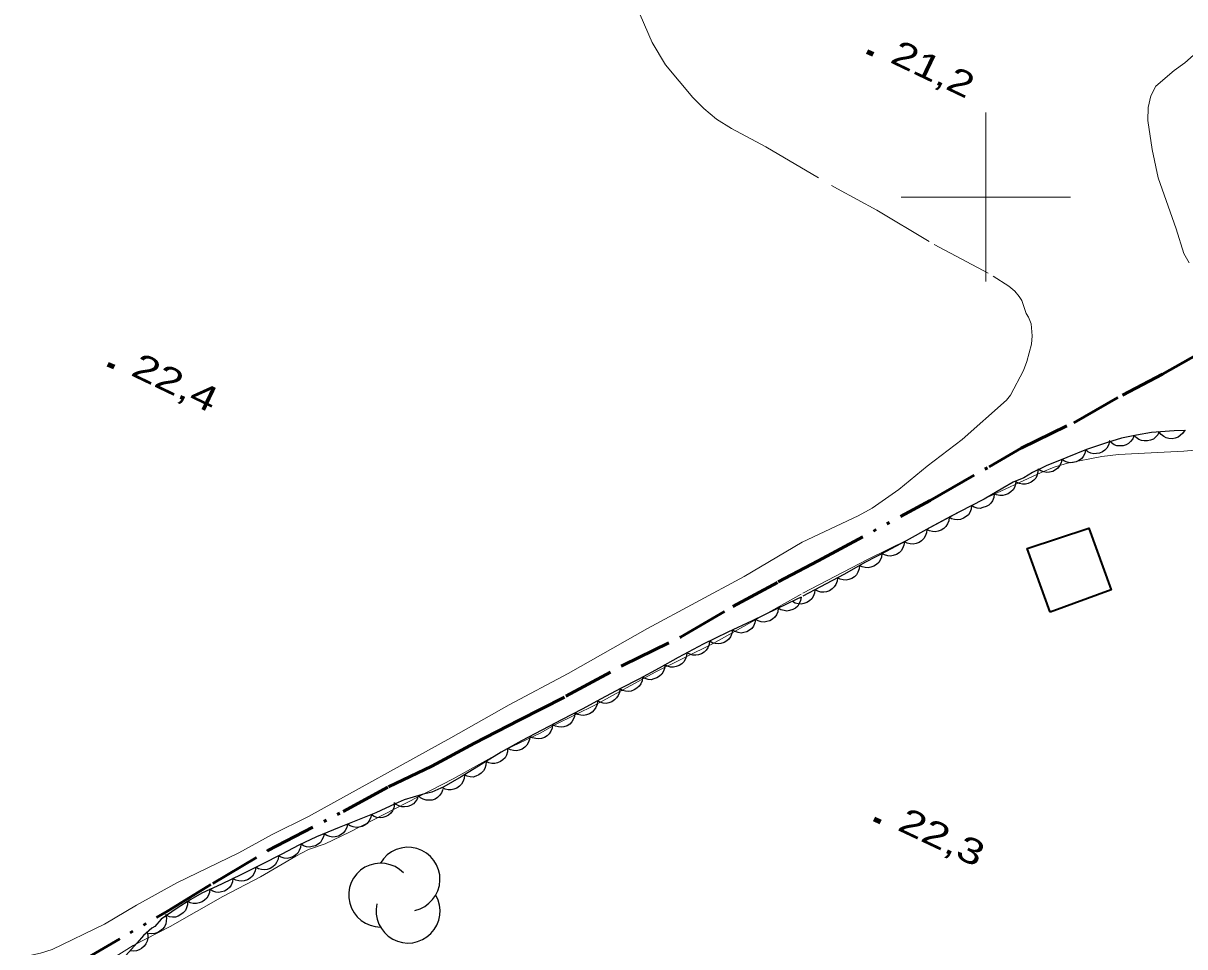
# Model space of a CAD drawing. Extents: x 356765 to 358572, y 5103174 to 5104650.
# Drawn here: x 357043.2 to 357111.7, y 5104255.7 to 5104310.3 of the extents above; entities that cross this region are included whole.
import ezdxf

# ---------------------------------------------------------------- set-up
doc = ezdxf.new("R2010")
doc.units = 0
doc.header["$LTSCALE"] = 0.6
for name, pattern in [('DASH_DOUBLE_DOT', [9.2, 5, -1.2, 0.3, -1.2, 0.3, -1.2]), ('DOT_DASHED', [7.7, 5, -1.2, 0.3, -1.2]), ('LONG_DASHED', [7.5, 6, -1.5])]:
    doc.linetypes.add(name, pattern=pattern)
for name, color, linetype, lineweight in [('2', 7, 'Continuous', 13), ('3', 7, 'Continuous', 140), ('31', 7, 'Continuous', 70), ('4', 7, 'Continuous', 90), ('44', 7, 'Continuous', 25), ('61', 7, 'Continuous', 13)]:
    doc.layers.add(name, color=color, linetype=linetype, lineweight=lineweight)

msp = doc.modelspace()

# ---------------------------------------------------------------- linework, layer by layer
at = {"layer": '2', "linetype": 'LONG_DASHED'}
for points in [[(357079.59, 5104310.76), (357080.31, 5104309.13), (357081.09, 5104307.8), (357082.7, 5104305.87), (357083.36, 5104305.22), (357084.11, 5104304.59), (357084.98, 5104304.05), (357087.02, 5104302.96), (357091.24, 5104300.48), (357093.57, 5104299.23), (357096.96, 5104297.2), (357100.44, 5104295.33), (357101.35, 5104294.74), (357101.71, 5104294.43), (357101.96, 5104294.13), (357102.12, 5104293.88), (357102.38, 5104293.12), (357102.53, 5104292.9), (357102.67, 5104292.51), (357102.73, 5104291.79), (357102.69, 5104291.3), (357102.43, 5104290.28), (357102.23, 5104289.76), (357101.45, 5104288.3), (357101.23, 5104287.99)], [(357112.01, 5104296.12), (357111.69, 5104296.67), (357111.24, 5104298.11), (357110.18, 5104301.13), (357109.82, 5104302.8), (357109.57, 5104304.51), (357109.59, 5104305.28), (357109.74, 5104305.97), (357110.04, 5104306.54), (357111.11, 5104307.48), (357111.74, 5104307.92), (357112.27, 5104308.38)]]:
    msp.add_lwpolyline(points, dxfattribs=at)
at = {"layer": '2'}
for points in [[(357126.22, 5104296.62), (357124.12, 5104295), (357123.48, 5104294.44), (357122.62, 5104293.59), (357121.99, 5104292.88), (357121.01, 5104291.3), (357120.74, 5104290.63), (357120.54, 5104289.91), (357120.33, 5104289.5), (357118.51, 5104286.99), (357118.07, 5104286.68), (357116.81, 5104286.18), (357113.43, 5104285.23), (357112.56, 5104285.07), (357111.68, 5104284.98), (357107.84, 5104284.79), (357106.84, 5104284.68), (357104.83, 5104284.28), (357104.04, 5104284.04), (357103.26, 5104283.73), (357099.86, 5104282.15), (357095.38, 5104279.75), (357093.01, 5104278.59), (357089.2, 5104276.59)], [(357043.18, 5104255.03), (357043.56, 5104255.2), (357044.2, 5104255.33), (357044.89, 5104255.55), (357047.98, 5104257.05), (357049.87, 5104258.18), (357052.24, 5104259.48), (357055.91, 5104261.26), (357057.87, 5104262.34), (357060.02, 5104263.41), (357068.42, 5104268.05), (357071.86, 5104270.01), (357075.34, 5104271.86), (357080.04, 5104274.51), (357085.73, 5104277.58), (357089.17, 5104279.61), (357092.47, 5104281.17), (357093.29, 5104281.63), (357094.86, 5104282.73), (357096.54, 5104284.11), (357098.6, 5104285.67), (357101.23, 5104287.99)], [(357089.1, 5104276.54), (357083.9, 5104273.62), (357080.48, 5104271.93), (357076.96, 5104270.01), (357074.56, 5104268.82), (357073.69, 5104268.33), (357071.67, 5104267.36), (357068.56, 5104265.63), (357062.43, 5104262.49), (357061, 5104261.8), (357060.02, 5104261.46), (357059.28, 5104261.07), (357057.18, 5104259.84), (357054.96, 5104258.69), (357051.86, 5104256.92), (357049.67, 5104255.79), (357047.76, 5104254.59), (357046.74, 5104254.01), (357044.55, 5104252.92)]]:
    msp.add_lwpolyline(points, dxfattribs=at)
at = {"layer": '3'}
for p, q in [((357092.99, 5104308.6), (357093.35, 5104308.43)), ((357048.18, 5104290.13), (357048.54, 5104289.96)), ((357093.41, 5104263.27), (357093.78, 5104263.1))]:
    msp.add_line(p, q, dxfattribs=at)
at = {"layer": '31', "lineweight": 35}
msp.add_lwpolyline([(357103.79, 5104275.48), (357102.45, 5104279.24), (357106.08, 5104280.43), (357107.41, 5104276.8), (357103.79, 5104275.48)], close=True, dxfattribs=at)
at = {"layer": '4', "linetype": 'DASH_DOUBLE_DOT', "lineweight": 53}
msp.add_lwpolyline([(357046.29, 5104254.66), (357051.69, 5104257.82), (357054.38, 5104259.46), (357057.62, 5104261.39), (357062.07, 5104263.71), (357064.74, 5104265.16), (357067.3, 5104266.39), (357069.82, 5104267.73), (357072.45, 5104269.1), (357075.21, 5104270.51), (357078.6, 5104272.35), (357081.98, 5104274), (357085.06, 5104275.81), (357087.74, 5104277.26), (357090.1, 5104278.5), (357096.72, 5104282.07), (357100.19, 5104284.06), (357102.09, 5104285.16), (357105.19, 5104286.67), (357108.07, 5104288.3), (357110.43, 5104289.54), (357112.88, 5104290.92)], dxfattribs=at)
at = {"layer": '44', "linetype": 'DOT_DASHED'}
for points in [[(357111.79, 5104286.21), (357111.11, 5104286.18), (357109.78, 5104286.08), (357108.89, 5104285.94), (357108.02, 5104285.75), (357107.18, 5104285.5), (357105.95, 5104285.08), (357104.79, 5104284.62), (357103.56, 5104284.12), (357102.75, 5104283.73), (357102.24, 5104283.41), (357101.61, 5104283.15), (357101.01, 5104282.8), (357099.9, 5104282.15), (357099.09, 5104281.73), (357097.95, 5104281.15), (357096.68, 5104280.46), (357095.3, 5104279.69), (357094.11, 5104279.07), (357092.9, 5104278.43), (357091.61, 5104277.71), (357090.25, 5104276.97), (357089.2, 5104276.42)], [(357089.1, 5104276.37), (357088.8, 5104276.22), (357087.67, 5104275.67), (357086.21, 5104274.96), (357084.77, 5104274.29), (357083.32, 5104273.58), (357081.84, 5104272.8), (357080.71, 5104272.17), (357079.56, 5104271.54), (357078.43, 5104270.96), (357077.3, 5104270.36), (357076.17, 5104269.75), (357075, 5104269.13), (357073.8, 5104268.51), (357072.59, 5104267.88), (357071.4, 5104267.2), (357070.21, 5104266.47), (357069.04, 5104265.75), (357068, 5104265.16), (357067.29, 5104264.84), (357066.72, 5104264.7), (357065.67, 5104264.4), (357065.14, 5104264.15), (357064, 5104263.62), (357063.2, 5104263.3), (357061.82, 5104262.75), (357060.49, 5104262.2), (357059.44, 5104261.71), (357058.45, 5104261.19), (357057.25, 5104260.58), (357056.07, 5104259.99), (357054.88, 5104259.41), (357053.73, 5104258.87), (357053.07, 5104258.5), (357052.26, 5104257.99), (357051.32, 5104257.34), (357050.95, 5104256.92), (357050.78, 5104256.82), (357050.27, 5104256.38), (357049.9, 5104255.95), (357048.9, 5104254.83)]]:
    msp.add_lwpolyline(points, dxfattribs=at)
at = {"layer": '44'}
for points in [[(357108.76, 5104285.91), (357108.68, 5104285.72), (357108.55, 5104285.56), (357108.43, 5104285.44), (357108.28, 5104285.36), (357108.1, 5104285.31), (357107.91, 5104285.3), (357107.74, 5104285.31), (357107.58, 5104285.37), (357107.42, 5104285.47), (357107.29, 5104285.59)], [(357110.24, 5104286.15), (357110.15, 5104285.96), (357110.01, 5104285.81), (357109.89, 5104285.7), (357109.72, 5104285.63), (357109.54, 5104285.59), (357109.35, 5104285.59), (357109.19, 5104285.61), (357109.03, 5104285.68), (357108.88, 5104285.79), (357108.75, 5104285.92)], [(357111.74, 5104286.23), (357111.63, 5104286.05), (357111.48, 5104285.91), (357111.35, 5104285.81), (357111.18, 5104285.75), (357111, 5104285.72), (357110.81, 5104285.74), (357110.65, 5104285.77), (357110.5, 5104285.86), (357110.35, 5104285.97), (357110.24, 5104286.11)], [(357107.3, 5104285.54), (357107.25, 5104285.34), (357107.14, 5104285.17), (357107.03, 5104285.04), (357106.89, 5104284.94), (357106.72, 5104284.87), (357106.53, 5104284.84), (357106.37, 5104284.83), (357106.2, 5104284.87), (357106.03, 5104284.95), (357105.88, 5104285.06)], [(357104.49, 5104284.5), (357104.45, 5104284.29), (357104.35, 5104284.12), (357104.25, 5104283.98), (357104.11, 5104283.88), (357103.95, 5104283.79), (357103.76, 5104283.75), (357103.6, 5104283.73), (357103.42, 5104283.77), (357103.25, 5104283.83), (357103.1, 5104283.93)], [(357105.88, 5104285.05), (357105.84, 5104284.85), (357105.74, 5104284.67), (357105.64, 5104284.54), (357105.5, 5104284.44), (357105.33, 5104284.35), (357105.15, 5104284.31), (357104.98, 5104284.3), (357104.81, 5104284.33), (357104.64, 5104284.4), (357104.49, 5104284.5)], [(357103.09, 5104283.94), (357103.08, 5104283.74), (357103.02, 5104283.54), (357102.95, 5104283.4), (357102.83, 5104283.27), (357102.68, 5104283.16), (357102.5, 5104283.08), (357102.34, 5104283.04), (357102.17, 5104283.04), (357101.99, 5104283.07), (357101.82, 5104283.15)], [(357101.77, 5104283.24), (357101.76, 5104283.04), (357101.69, 5104282.85), (357101.61, 5104282.7), (357101.48, 5104282.58), (357101.33, 5104282.47), (357101.15, 5104282.4), (357101, 5104282.36), (357100.82, 5104282.37), (357100.64, 5104282.41), (357100.48, 5104282.49)], [(357100.49, 5104282.46), (357100.47, 5104282.25), (357100.39, 5104282.06), (357100.3, 5104281.92), (357100.17, 5104281.8), (357100.02, 5104281.71), (357099.83, 5104281.65), (357099.67, 5104281.61), (357099.5, 5104281.63), (357099.32, 5104281.68), (357099.16, 5104281.77)], [(357099.16, 5104281.77), (357099.14, 5104281.56), (357099.05, 5104281.37), (357098.97, 5104281.23), (357098.84, 5104281.12), (357098.68, 5104281.02), (357098.5, 5104280.96), (357098.34, 5104280.93), (357098.16, 5104280.95), (357097.98, 5104281), (357097.83, 5104281.09)], [(357097.83, 5104281.08), (357097.81, 5104280.88), (357097.73, 5104280.69), (357097.65, 5104280.54), (357097.52, 5104280.42), (357097.36, 5104280.32), (357097.18, 5104280.26), (357097.02, 5104280.22), (357096.85, 5104280.24), (357096.67, 5104280.28), (357096.51, 5104280.37)], [(357096.51, 5104280.37), (357096.49, 5104280.16), (357096.42, 5104279.97), (357096.34, 5104279.82), (357096.21, 5104279.7), (357096.06, 5104279.6), (357095.88, 5104279.53), (357095.72, 5104279.5), (357095.54, 5104279.51), (357095.36, 5104279.55), (357095.2, 5104279.63)], [(357095.2, 5104279.64), (357095.17, 5104279.43), (357095.09, 5104279.24), (357095.01, 5104279.1), (357094.88, 5104278.98), (357094.72, 5104278.88), (357094.54, 5104278.83), (357094.38, 5104278.79), (357094.21, 5104278.81), (357094.03, 5104278.86), (357093.87, 5104278.94)], [(357093.87, 5104278.94), (357093.85, 5104278.73), (357093.77, 5104278.55), (357093.68, 5104278.41), (357093.55, 5104278.29), (357093.4, 5104278.19), (357093.22, 5104278.13), (357093.06, 5104278.09), (357092.88, 5104278.11), (357092.7, 5104278.16), (357092.54, 5104278.24)], [(357092.55, 5104278.23), (357092.53, 5104278.03), (357092.45, 5104277.84), (357092.37, 5104277.69), (357092.25, 5104277.57), (357092.09, 5104277.47), (357091.91, 5104277.4), (357091.75, 5104277.36), (357091.58, 5104277.38), (357091.4, 5104277.42), (357091.24, 5104277.5)], [(357091.24, 5104277.51), (357091.22, 5104277.3), (357091.14, 5104277.11), (357091.05, 5104276.97), (357090.93, 5104276.85), (357090.77, 5104276.74), (357090.59, 5104276.68), (357090.43, 5104276.65), (357090.26, 5104276.66), (357090.08, 5104276.71), (357089.92, 5104276.79)], [(357089.1, 5104276.37), (357089.07, 5104276.16), (357088.99, 5104275.98), (357088.9, 5104275.84), (357088.76, 5104275.72), (357088.61, 5104275.63), (357088.42, 5104275.57), (357088.26, 5104275.54), (357088.09, 5104275.57), (357087.91, 5104275.62), (357087.75, 5104275.71)], [(357089.91, 5104276.79), (357089.89, 5104276.59), (357089.81, 5104276.4), (357089.73, 5104276.26), (357089.6, 5104276.14), (357089.44, 5104276.04), (357089.26, 5104275.98), (357089.1, 5104275.95), (357088.92, 5104275.96), (357088.74, 5104276.01), (357088.59, 5104276.1)], [(357087.75, 5104275.71), (357087.72, 5104275.5), (357087.64, 5104275.32), (357087.55, 5104275.18), (357087.41, 5104275.07), (357087.26, 5104274.97), (357087.07, 5104274.92), (357086.91, 5104274.89), (357086.74, 5104274.91), (357086.56, 5104274.96), (357086.4, 5104275.05)], [(357086.41, 5104275.05), (357086.37, 5104274.84), (357086.28, 5104274.66), (357086.19, 5104274.52), (357086.06, 5104274.41), (357085.9, 5104274.32), (357085.71, 5104274.27), (357085.55, 5104274.24), (357085.38, 5104274.27), (357085.2, 5104274.33), (357085.05, 5104274.42)], [(357085.04, 5104274.42), (357085.01, 5104274.22), (357084.93, 5104274.03), (357084.84, 5104273.89), (357084.71, 5104273.78), (357084.55, 5104273.68), (357084.36, 5104273.63), (357084.2, 5104273.6), (357084.03, 5104273.62), (357083.85, 5104273.67), (357083.7, 5104273.76)], [(357083.69, 5104273.78), (357083.67, 5104273.57), (357083.59, 5104273.38), (357083.5, 5104273.24), (357083.37, 5104273.12), (357083.22, 5104273.02), (357083.04, 5104272.96), (357082.88, 5104272.93), (357082.7, 5104272.94), (357082.52, 5104272.99), (357082.36, 5104273.08)], [(357082.36, 5104273.09), (357082.34, 5104272.88), (357082.26, 5104272.69), (357082.18, 5104272.55), (357082.06, 5104272.43), (357081.9, 5104272.32), (357081.72, 5104272.26), (357081.56, 5104272.22), (357081.39, 5104272.23), (357081.21, 5104272.28), (357081.05, 5104272.36)], [(357081.05, 5104272.36), (357081.03, 5104272.15), (357080.95, 5104271.96), (357080.87, 5104271.82), (357080.74, 5104271.69), (357080.59, 5104271.59), (357080.41, 5104271.53), (357080.25, 5104271.49), (357080.07, 5104271.51), (357079.89, 5104271.55), (357079.73, 5104271.63)], [(357079.73, 5104271.63), (357079.71, 5104271.42), (357079.63, 5104271.24), (357079.54, 5104271.1), (357079.41, 5104270.98), (357079.25, 5104270.88), (357079.07, 5104270.82), (357078.91, 5104270.79), (357078.74, 5104270.81), (357078.56, 5104270.86), (357078.4, 5104270.94)], [(357078.4, 5104270.94), (357078.38, 5104270.74), (357078.3, 5104270.55), (357078.21, 5104270.41), (357078.09, 5104270.29), (357077.93, 5104270.19), (357077.75, 5104270.13), (357077.59, 5104270.09), (357077.41, 5104270.11), (357077.23, 5104270.16), (357077.08, 5104270.24)], [(357077.08, 5104270.24), (357077.06, 5104270.03), (357076.98, 5104269.84), (357076.89, 5104269.7), (357076.77, 5104269.58), (357076.61, 5104269.48), (357076.43, 5104269.42), (357076.27, 5104269.38), (357076.1, 5104269.4), (357075.92, 5104269.44), (357075.76, 5104269.53)], [(357075.75, 5104269.53), (357075.73, 5104269.32), (357075.65, 5104269.14), (357075.57, 5104268.99), (357075.44, 5104268.87), (357075.28, 5104268.77), (357075.1, 5104268.71), (357074.94, 5104268.68), (357074.77, 5104268.7), (357074.59, 5104268.74), (357074.43, 5104268.83)], [(357074.43, 5104268.84), (357074.4, 5104268.63), (357074.32, 5104268.44), (357074.23, 5104268.3), (357074.1, 5104268.18), (357073.95, 5104268.08), (357073.77, 5104268.02), (357073.61, 5104267.99), (357073.43, 5104268.01), (357073.25, 5104268.06), (357073.09, 5104268.14)], [(357073.08, 5104268.16), (357073.07, 5104267.95), (357072.99, 5104267.76), (357072.91, 5104267.62), (357072.79, 5104267.5), (357072.64, 5104267.39), (357072.46, 5104267.33), (357072.3, 5104267.29), (357072.12, 5104267.3), (357071.94, 5104267.34), (357071.78, 5104267.42)], [(357071.77, 5104267.43), (357071.77, 5104267.22), (357071.7, 5104267.03), (357071.62, 5104266.88), (357071.5, 5104266.76), (357071.35, 5104266.65), (357071.17, 5104266.57), (357071.02, 5104266.53), (357070.84, 5104266.54), (357070.66, 5104266.57), (357070.5, 5104266.65)], [(357070.5, 5104266.65), (357070.49, 5104266.44), (357070.42, 5104266.25), (357070.34, 5104266.1), (357070.22, 5104265.97), (357070.07, 5104265.86), (357069.9, 5104265.79), (357069.74, 5104265.74), (357069.56, 5104265.75), (357069.38, 5104265.79), (357069.22, 5104265.86)], [(357069.22, 5104265.85), (357069.21, 5104265.65), (357069.13, 5104265.46), (357069.05, 5104265.31), (357068.93, 5104265.19), (357068.77, 5104265.08), (357068.59, 5104265.02), (357068.44, 5104264.98), (357068.26, 5104264.99), (357068.08, 5104265.03), (357067.92, 5104265.11)], [(357066.5, 5104264.64), (357066.43, 5104264.44), (357066.32, 5104264.27), (357066.21, 5104264.15), (357066.05, 5104264.06), (357065.88, 5104263.99), (357065.69, 5104263.97), (357065.53, 5104263.97), (357065.36, 5104264.03), (357065.2, 5104264.11), (357065.06, 5104264.22)], [(357067.95, 5104265), (357067.88, 5104264.81), (357067.76, 5104264.65), (357067.64, 5104264.53), (357067.49, 5104264.44), (357067.31, 5104264.38), (357067.12, 5104264.37), (357066.96, 5104264.38), (357066.79, 5104264.43), (357066.63, 5104264.52), (357066.5, 5104264.65)], [(357065.09, 5104264.13), (357065.06, 5104263.92), (357064.97, 5104263.74), (357064.88, 5104263.6), (357064.74, 5104263.49), (357064.58, 5104263.4), (357064.4, 5104263.35), (357064.24, 5104263.32), (357064.06, 5104263.35), (357063.89, 5104263.4), (357063.73, 5104263.5)], [(357063.73, 5104263.51), (357063.68, 5104263.31), (357063.58, 5104263.13), (357063.48, 5104263), (357063.34, 5104262.89), (357063.18, 5104262.81), (357062.99, 5104262.77), (357062.83, 5104262.75), (357062.66, 5104262.79), (357062.48, 5104262.85), (357062.33, 5104262.95)], [(357062.33, 5104262.96), (357062.29, 5104262.76), (357062.19, 5104262.58), (357062.09, 5104262.44), (357061.95, 5104262.34), (357061.79, 5104262.25), (357061.6, 5104262.21), (357061.44, 5104262.19), (357061.27, 5104262.22), (357061.1, 5104262.29), (357060.95, 5104262.39)], [(357059.57, 5104261.78), (357059.55, 5104261.57), (357059.47, 5104261.39), (357059.39, 5104261.24), (357059.26, 5104261.13), (357059.1, 5104261.03), (357058.92, 5104260.97), (357058.76, 5104260.93), (357058.58, 5104260.95), (357058.4, 5104261), (357058.25, 5104261.08)], [(357060.94, 5104262.41), (357060.9, 5104262.2), (357060.81, 5104262.02), (357060.72, 5104261.88), (357060.59, 5104261.77), (357060.43, 5104261.68), (357060.24, 5104261.63), (357060.08, 5104261.6), (357059.91, 5104261.62), (357059.73, 5104261.68), (357059.58, 5104261.77)], [(357058.24, 5104261.09), (357058.22, 5104260.88), (357058.14, 5104260.69), (357058.05, 5104260.55), (357057.92, 5104260.43), (357057.76, 5104260.34), (357057.58, 5104260.28), (357057.42, 5104260.25), (357057.24, 5104260.27), (357057.06, 5104260.32), (357056.91, 5104260.41)], [(357056.91, 5104260.41), (357056.88, 5104260.2), (357056.79, 5104260.02), (357056.71, 5104259.88), (357056.58, 5104259.76), (357056.42, 5104259.66), (357056.23, 5104259.61), (357056.07, 5104259.58), (357055.9, 5104259.6), (357055.72, 5104259.65), (357055.56, 5104259.74)], [(357055.56, 5104259.74), (357055.53, 5104259.54), (357055.45, 5104259.35), (357055.36, 5104259.21), (357055.22, 5104259.1), (357055.07, 5104259), (357054.88, 5104258.95), (357054.72, 5104258.92), (357054.55, 5104258.94), (357054.37, 5104259), (357054.21, 5104259.09)], [(357054.19, 5104259.13), (357054.17, 5104258.92), (357054.1, 5104258.73), (357054.02, 5104258.59), (357053.89, 5104258.47), (357053.74, 5104258.36), (357053.56, 5104258.3), (357053.4, 5104258.26), (357053.22, 5104258.27), (357053.04, 5104258.31), (357052.88, 5104258.4)], [(357052.87, 5104258.41), (357052.87, 5104258.2), (357052.82, 5104258.01), (357052.75, 5104257.86), (357052.63, 5104257.72), (357052.49, 5104257.61), (357052.32, 5104257.53), (357052.16, 5104257.47), (357051.99, 5104257.47), (357051.81, 5104257.49), (357051.64, 5104257.56)], [(357051.58, 5104257.63), (357051.63, 5104257.43), (357051.62, 5104257.22), (357051.59, 5104257.06), (357051.51, 5104256.9), (357051.4, 5104256.76), (357051.25, 5104256.63), (357051.12, 5104256.55), (357050.95, 5104256.5), (357050.76, 5104256.48), (357050.58, 5104256.5)], [(357050.48, 5104256.62), (357050.53, 5104256.42), (357050.53, 5104256.22), (357050.5, 5104256.05), (357050.42, 5104255.89), (357050.31, 5104255.74), (357050.17, 5104255.62), (357050.03, 5104255.53), (357049.86, 5104255.48), (357049.68, 5104255.46), (357049.5, 5104255.48)]]:
    msp.add_lwpolyline(points, dxfattribs=at)
for centre, start, end in [((357065.8974, 5104259.7055), 282.26917, 149.72626), ((357064.2761, 5104258.7628), 44.11537, 269.80396), ((357065.8974, 5104257.8202), 166.93686, 29.62122)]:
    msp.add_arc(centre, 1.8853, start, end, dxfattribs=at)
at = {"layer": '61'}
for p, q in [((357100, 5104295), (357100, 5104305)), ((357095, 5104300), (357105, 5104300))]:
    msp.add_line(p, q, dxfattribs=at)

# ---------------------------------------------------------------- texts
at = {"layer": '3'}
for s, rotation, width, p in [('21,2   ', 334.423, 1.3, (357094.28, 5104307.98)), ('22,4   ', 334.423, 1.35, (357049.46, 5104289.5)), ('22,3   ', 334.72, 1.35, (357094.71, 5104262.64))]:
    msp.add_text(s, height=1.5, rotation=rotation, dxfattribs=dict(at, width=width)).set_placement(p)

doc.saveas('drawing.dxf')
